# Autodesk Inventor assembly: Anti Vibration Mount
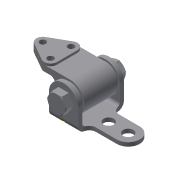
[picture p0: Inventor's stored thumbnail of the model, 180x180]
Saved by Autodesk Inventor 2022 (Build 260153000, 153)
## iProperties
Created: 2011-07
Part Number: Anti Vibration Mount
Document SubType Name: Assembly
Designer: CadCim
Author: CadCim
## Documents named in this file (5)
- D:\PROJECTS_2021\Resources\Tutorial Files\c09_Inv_2022_tut\c09_Inv_2022_tut\c09_Inv_tut_2022\c09_tut03_inv\Anti Vibration Mount\Anti Vibration Mount.iam
- D:\PROJECTS_2021\Resources\Tutorial Files\c09_Inv_2022_tut\c09_Inv_2022_tut\c09_Inv_tut_2022\c09_tut03_inv\Anti Vibration Mount\Yoke Plate.ipt
- D:\PROJECTS_2021\Resources\Tutorial Files\c09_Inv_2022_tut\c09_Inv_2022_tut\c09_Inv_tut_2022\c09_tut03_inv\Anti Vibration Mount\Body-Bushing Ruber.iam
- D:\PROJECTS_2021\Resources\Tutorial Files\c09_Inv_2022_tut\c09_Inv_2022_tut\c09_Inv_tut_2022\c09_tut03_inv\Anti Vibration Mount\Hex Bolt.ipt
- D:\PROJECTS_2021\Resources\Tutorial Files\c09_Inv_2022_tut\c09_Inv_2022_tut\c09_Inv_tut_2022\c09_tut03_inv\Anti Vibration Mount\Nut.ipt
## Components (4 placed, 4 different names)
1. Yoke Plate:1 — Insert:1, Angle:1, Mate:1, Mate:2, Mate:3
2. Body-Bushing Ruber:1 [sub-assembly] — Insert:1, Angle:1
3. Hex Bolt:1 — Mate:2, Mate:3, Mate:4
4. Nut:1 — Mate:1, Mate:4
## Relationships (6: Mate 4, Insert 1, Angle 1)
- Insert:1: Yoke Plate:1 ↔ Body-Bushing Ruber:1
- Angle:1: Yoke Plate:1 ↔ Body-Bushing Ruber:1
- Mate:1: Yoke Plate:1 ↔ Nut:1
- Mate:2: Yoke Plate:1 ↔ Hex Bolt:1
- Mate:3: Yoke Plate:1 ↔ Hex Bolt:1
- Mate:4: Hex Bolt:1 ↔ Nut:1
